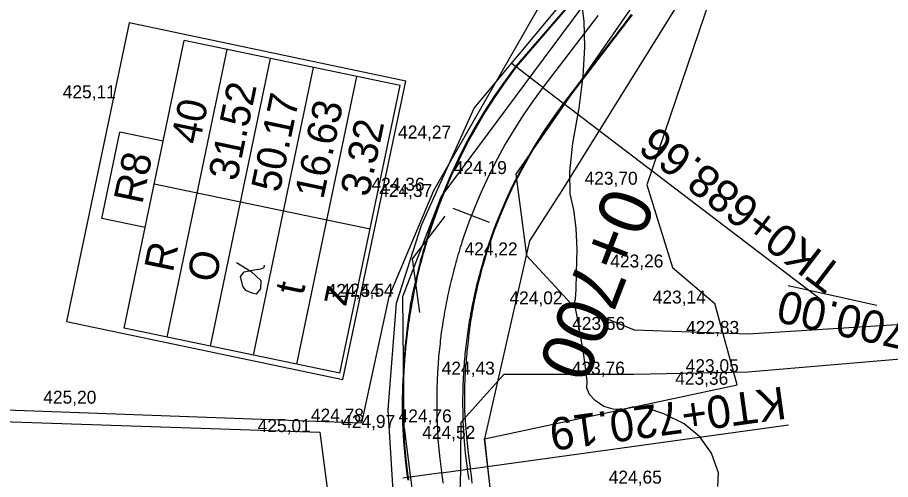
# Model space of a CAD drawing. Extents: x -574342 to -507939, y -1144044 to -1123894.
# Drawn here: x -508582.8 to -508515.5, y -1143739.5 to -1143703.9 of the extents above; entities that cross this region are included whole.
import ezdxf

# ---------------------------------------------------------------- set-up
doc = ezdxf.new("R2010")
doc.units = 0
for name, color, linetype in [('01_PARCELY_NAVRH_PC', 7, 'Continuous'), ('1000', 7, 'Continuous'), ('18', 7, 'Continuous'), ('19', 7, 'Continuous'), ('21', 7, 'Continuous'), ('23', 7, 'Continuous'), ('42', 7, 'Continuous'), ('55', 7, 'Continuous'), ('6', 7, 'Continuous'), ('Level 255', 7, 'Continuous'), ('SO 101_popis oblouku', 7, 'Continuous'), ('tab', 7, 'Continuous'), ('VRST VEDL', 7, 'Continuous')]:
    doc.layers.add(name, color=color, linetype=linetype)

msp = doc.modelspace()

# ---------------------------------------------------------------- linework, layer by layer
msp.add_lwpolyline([(-508557.691, -1143731.784), (-508552.841, -1143708.769), (-508574.145, -1143704.279), (-508578.996, -1143727.293)], close=True)
at = {"layer": '01_PARCELY_NAVRH_PC'}
for points in [[(-508550.74, -1143812.56), (-508547.51, -1143799.72), (-508547.8, -1143787.43), (-508554.08, -1143749.16), (-508553.41, -1143747.02), (-508554.21, -1143734.12), (-508553.55, -1143725.9), (-508551.64, -1143719.89), (-508547.57, -1143710.87), (-508540.84, -1143702.78), (-508531.01, -1143689.84), (-508528.88, -1143683.95), (-508518.64, -1143667.59), (-508513.88, -1143662.3), (-508507.94, -1143646.93), (-508502.84, -1143629.47), (-508500.33, -1143614.14), (-508495.09, -1143559.2), (-508493.85, -1143537.59)], [(-508550.74, -1143812.56), (-508547.51, -1143799.72), (-508547.8, -1143787.43), (-508554.08, -1143749.16), (-508553.41, -1143747.02), (-508554.21, -1143734.12), (-508553.55, -1143725.9), (-508551.64, -1143719.89), (-508547.57, -1143710.87), (-508540.84, -1143702.78), (-508531.01, -1143689.84), (-508528.88, -1143683.95), (-508518.64, -1143667.59), (-508513.88, -1143662.3), (-508507.94, -1143646.93), (-508502.84, -1143629.47), (-508500.33, -1143614.14), (-508495.09, -1143559.2), (-508493.85, -1143537.59)], [(-508488.59, -1143541.43), (-508489.82, -1143560.44), (-508491.6, -1143582.01), (-508495.73, -1143620.81), (-508499.42, -1143638.98), (-508505.75, -1143657.81), (-508517.46, -1143682.4), (-508526.71, -1143694.52), (-508540.76, -1143717.14), (-508543.32, -1143721.09), (-508546.79, -1143736.35), (-508545.73, -1143746.01), (-508540.36, -1143791.5), (-508536.1, -1143827.99)], [(-508488.59, -1143541.43), (-508489.82, -1143560.44), (-508491.6, -1143582.01), (-508495.73, -1143620.81), (-508499.42, -1143638.98), (-508505.75, -1143657.81), (-508517.46, -1143682.4), (-508526.71, -1143694.52), (-508540.76, -1143717.14), (-508543.32, -1143721.09), (-508546.79, -1143736.35), (-508545.73, -1143746.01), (-508540.36, -1143791.5), (-508536.1, -1143827.99)]]:
    msp.add_lwpolyline(points, dxfattribs=at)
at = {"layer": '1000'}
for points in [[(-508540.235, -1143702.843), (-508544.388, -1143707.644), (-508544.389, -1143707.645), (-508545.223, -1143708.771), (-508546.02, -1143709.923), (-508546.78, -1143711.1), (-508547.501, -1143712.302), (-508548.184, -1143713.526), (-508548.812, -1143714.779), (-508549.4, -1143716.051), (-508549.946, -1143717.341), (-508550.271, -1143718.166), (-508550.452, -1143718.647), (-508550.917, -1143719.969), (-508551.049, -1143720.373), (-508551.116, -1143720.581), (-508551.182, -1143720.79), (-508551.246, -1143720.999), (-508551.31, -1143721.208), (-508551.339, -1143721.304), (-508551.373, -1143721.417), (-508551.435, -1143721.627), (-508551.496, -1143721.837), (-508551.556, -1143722.047), (-508551.615, -1143722.258), (-508551.673, -1143722.469), (-508551.723, -1143722.652), (-508551.731, -1143722.68), (-508551.787, -1143722.891), (-508551.842, -1143723.102), (-508551.896, -1143723.314), (-508551.95, -1143723.526), (-508552.002, -1143723.739), (-508552.054, -1143723.951), (-508552.068, -1143724.01), (-508552.104, -1143724.164), (-508552.154, -1143724.377), (-508552.202, -1143724.59), (-508552.25, -1143724.804), (-508552.297, -1143725.018), (-508552.342, -1143725.232), (-508552.371, -1143725.378), (-508552.385, -1143725.446), (-508552.427, -1143725.661), (-508552.468, -1143725.876), (-508552.502, -1143726.092), (-508552.535, -1143726.308), (-508552.567, -1143726.525), (-508552.599, -1143726.741), (-508552.602, -1143726.761), (-508552.63, -1143726.958), (-508552.659, -1143727.175), (-508552.688, -1143727.391), (-508552.716, -1143727.608), (-508552.743, -1143727.825), (-508552.769, -1143728.042), (-508552.781, -1143728.15), (-508552.794, -1143728.26), (-508552.818, -1143728.477), (-508552.841, -1143728.694), (-508552.863, -1143728.912), (-508552.884, -1143729.129), (-508552.904, -1143729.347), (-508552.921, -1143729.544), (-508552.923, -1143729.565), (-508552.941, -1143729.783), (-508552.958, -1143730), (-508552.974, -1143730.218), (-508552.989, -1143730.436), (-508553.004, -1143730.654), (-508553.017, -1143730.873), (-508553.022, -1143730.941), (-508553.031, -1143731.091), (-508553.044, -1143731.309), (-508553.056, -1143731.527), (-508553.067, -1143731.745), (-508553.077, -1143731.964), (-508553.085, -1143732.182), (-508553.091, -1143732.339), (-508553.093, -1143732.4), (-508553.099, -1143732.619), (-508553.105, -1143732.837), (-508553.109, -1143733.056), (-508553.112, -1143733.274), (-508553.114, -1143733.493), (-508553.115, -1143733.712), (-508553.115, -1143733.739), (-508553.115, -1143733.93), (-508553.114, -1143734.149), (-508553.112, -1143734.368), (-508553.108, -1143734.586), (-508553.104, -1143734.805), (-508553.098, -1143735.023), (-508553.095, -1143735.14), (-508553.022, -1143736.539), (-508552.899, -1143737.935), (-508552.739, -1143739.24), (-508552.727, -1143739.325), (-508552.726, -1143739.33), (-508552.684, -1143739.537)], [(-508540.196, -1143702.873), (-508544.339, -1143707.682), (-508544.34, -1143707.682), (-508545.17, -1143708.809), (-508545.962, -1143709.961), (-508546.716, -1143711.14), (-508547.431, -1143712.342), (-508548.106, -1143713.567), (-508548.74, -1143714.814), (-508549.333, -1143716.081), (-508549.885, -1143717.366), (-508550.212, -1143718.189), (-508550.393, -1143718.669), (-508550.859, -1143719.988), (-508550.992, -1143720.392), (-508551.059, -1143720.6), (-508551.124, -1143720.808), (-508551.189, -1143721.016), (-508551.252, -1143721.225), (-508551.281, -1143721.322), (-508551.315, -1143721.435), (-508551.376, -1143721.644), (-508551.436, -1143721.854), (-508551.496, -1143722.064), (-508551.554, -1143722.275), (-508551.611, -1143722.485), (-508551.659, -1143722.669), (-508551.667, -1143722.696), (-508551.722, -1143722.908), (-508551.775, -1143723.119), (-508551.828, -1143723.331), (-508551.88, -1143723.543), (-508551.93, -1143723.756), (-508551.98, -1143723.968), (-508551.993, -1143724.027), (-508552.028, -1143724.181), (-508552.075, -1143724.394), (-508552.122, -1143724.608), (-508552.167, -1143724.821), (-508552.211, -1143725.035), (-508552.253, -1143725.249), (-508552.282, -1143725.396), (-508552.295, -1143725.464), (-508552.336, -1143725.678), (-508552.376, -1143725.893), (-508552.414, -1143726.108), (-508552.451, -1143726.323), (-508552.488, -1143726.538), (-508552.523, -1143726.754), (-508552.526, -1143726.773), (-508552.557, -1143726.969), (-508552.59, -1143727.185), (-508552.622, -1143727.401), (-508552.653, -1143727.617), (-508552.682, -1143727.833), (-508552.711, -1143728.05), (-508552.724, -1143728.158), (-508552.738, -1143728.267), (-508552.764, -1143728.483), (-508552.79, -1143728.7), (-508552.814, -1143728.917), (-508552.837, -1143729.134), (-508552.859, -1143729.351), (-508552.877, -1143729.548), (-508552.879, -1143729.569), (-508552.899, -1143729.786), (-508552.917, -1143730.004), (-508552.935, -1143730.221), (-508552.951, -1143730.439), (-508552.966, -1143730.657), (-508552.98, -1143730.875), (-508552.985, -1143730.943), (-508552.993, -1143731.093), (-508553.005, -1143731.311), (-508553.016, -1143731.529), (-508553.026, -1143731.747), (-508553.034, -1143731.965), (-508553.041, -1143732.183), (-508553.046, -1143732.34), (-508553.048, -1143732.402), (-508553.053, -1143732.62), (-508553.057, -1143732.838), (-508553.06, -1143733.056), (-508553.061, -1143733.275), (-508553.062, -1143733.493), (-508553.062, -1143733.711), (-508553.061, -1143733.739), (-508553.06, -1143733.93), (-508553.057, -1143734.148), (-508553.053, -1143734.366), (-508553.048, -1143734.585), (-508553.042, -1143734.803), (-508553.035, -1143735.021), (-508553.031, -1143735.137), (-508552.955, -1143736.534), (-508552.832, -1143737.928), (-508552.676, -1143739.231), (-508552.664, -1143739.316), (-508552.664, -1143739.321), (-508552.622, -1143739.528)], [(-508535.464, -1143703.627), (-508535.66, -1143703.885), (-508535.857, -1143704.142), (-508536.053, -1143704.4), (-508536.25, -1143704.658), (-508536.447, -1143704.916), (-508536.643, -1143705.174), (-508536.84, -1143705.432), (-508540.681, -1143710.47), (-508540.682, -1143710.471), (-508541.422, -1143711.476), (-508542.129, -1143712.504), (-508542.801, -1143713.555), (-508543.439, -1143714.628), (-508544.041, -1143715.721), (-508544.607, -1143716.833), (-508545.136, -1143717.963), (-508545.628, -1143719.109), (-508545.919, -1143719.843), (-508546.082, -1143720.272), (-508546.497, -1143721.448), (-508546.616, -1143721.808), (-508546.675, -1143721.994), (-508546.734, -1143722.179), (-508546.791, -1143722.365), (-508546.848, -1143722.552), (-508546.874, -1143722.638), (-508546.903, -1143722.738), (-508546.958, -1143722.925), (-508547.012, -1143723.113), (-508547.065, -1143723.3), (-508547.117, -1143723.488), (-508547.167, -1143723.676), (-508547.211, -1143723.839), (-508547.217, -1143723.864), (-508547.266, -1143724.052), (-508547.314, -1143724.241), (-508547.361, -1143724.43), (-508547.407, -1143724.619), (-508547.452, -1143724.809), (-508547.497, -1143724.999), (-508547.509, -1143725.051), (-508547.54, -1143725.188), (-508547.582, -1143725.379), (-508547.623, -1143725.569), (-508547.663, -1143725.76), (-508547.703, -1143725.95), (-508547.741, -1143726.141), (-508547.766, -1143726.272), (-508547.778, -1143726.332), (-508547.814, -1143726.524), (-508547.85, -1143726.715), (-508547.884, -1143726.907), (-508547.917, -1143727.099), (-508547.95, -1143727.291), (-508547.981, -1143727.483), (-508547.984, -1143727.5), (-508548.011, -1143727.675), (-508548.041, -1143727.868), (-508548.069, -1143728.061), (-508548.097, -1143728.253), (-508548.123, -1143728.446), (-508548.149, -1143728.639), (-508548.161, -1143728.736), (-508548.173, -1143728.833), (-508548.197, -1143729.026), (-508548.219, -1143729.219), (-508548.241, -1143729.413), (-508548.261, -1143729.607), (-508548.281, -1143729.8), (-508548.297, -1143729.976), (-508548.299, -1143729.994), (-508548.317, -1143730.188), (-508548.333, -1143730.382), (-508548.349, -1143730.577), (-508548.363, -1143730.771), (-508548.377, -1143730.965), (-508548.389, -1143731.159), (-508548.393, -1143731.22), (-508548.401, -1143731.354), (-508548.411, -1143731.548), (-508548.421, -1143731.743), (-508548.429, -1143731.937), (-508548.437, -1143732.132), (-508548.444, -1143732.327), (-508548.448, -1143732.467), (-508548.449, -1143732.521), (-508548.454, -1143732.716), (-508548.457, -1143732.911), (-508548.46, -1143733.105), (-508548.461, -1143733.3), (-508548.462, -1143733.495), (-508548.462, -1143733.69), (-508548.461, -1143733.714), (-508548.46, -1143733.884), (-508548.458, -1143734.079), (-508548.454, -1143734.274), (-508548.45, -1143734.469), (-508548.444, -1143734.663), (-508548.438, -1143734.858), (-508548.434, -1143734.962), (-508548.366, -1143736.208), (-508548.257, -1143737.451), (-508548.118, -1143738.613), (-508548.107, -1143738.689), (-508548.107, -1143738.694), (-508548.078, -1143738.903), (-508548.038, -1143739.197), (-508547.997, -1143739.49)], [(-508535.409, -1143703.668), (-508535.608, -1143703.925), (-508535.805, -1143704.182), (-508536.001, -1143704.44), (-508536.198, -1143704.698), (-508536.395, -1143704.955), (-508536.593, -1143705.213), (-508536.79, -1143705.47), (-508540.644, -1143710.499), (-508540.644, -1143710.5), (-508541.384, -1143711.503), (-508542.089, -1143712.531), (-508542.759, -1143713.581), (-508543.392, -1143714.655), (-508543.987, -1143715.749), (-508544.556, -1143716.858), (-508545.083, -1143717.986), (-508545.572, -1143719.132), (-508545.862, -1143719.865), (-508546.023, -1143720.294), (-508546.436, -1143721.469), (-508546.554, -1143721.828), (-508546.613, -1143722.013), (-508546.671, -1143722.199), (-508546.728, -1143722.385), (-508546.784, -1143722.571), (-508546.809, -1143722.657), (-508546.838, -1143722.758), (-508546.892, -1143722.944), (-508546.945, -1143723.132), (-508546.996, -1143723.319), (-508547.047, -1143723.507), (-508547.098, -1143723.694), (-508547.141, -1143723.858), (-508547.147, -1143723.882), (-508547.196, -1143724.071), (-508547.243, -1143724.259), (-508547.289, -1143724.448), (-508547.334, -1143724.637), (-508547.378, -1143724.826), (-508547.421, -1143725.016), (-508547.432, -1143725.068), (-508547.462, -1143725.206), (-508547.503, -1143725.396), (-508547.542, -1143725.586), (-508547.581, -1143725.777), (-508547.618, -1143725.967), (-508547.654, -1143726.158), (-508547.678, -1143726.289), (-508547.689, -1143726.349), (-508547.723, -1143726.541), (-508547.756, -1143726.732), (-508547.788, -1143726.924), (-508547.818, -1143727.116), (-508547.848, -1143727.308), (-508547.876, -1143727.5), (-508547.879, -1143727.517), (-508547.903, -1143727.692), (-508547.93, -1143727.885), (-508547.955, -1143728.077), (-508547.978, -1143728.27), (-508548.001, -1143728.463), (-508548.023, -1143728.656), (-508548.033, -1143728.752), (-508548.043, -1143728.849), (-508548.063, -1143729.042), (-508548.081, -1143729.235), (-508548.104, -1143729.428), (-508548.126, -1143729.621), (-508548.147, -1143729.814), (-508548.164, -1143729.988), (-508548.166, -1143730.007), (-508548.185, -1143730.2), (-508548.202, -1143730.393), (-508548.218, -1143730.587), (-508548.234, -1143730.78), (-508548.247, -1143730.974), (-508548.26, -1143731.167), (-508548.264, -1143731.228), (-508548.272, -1143731.361), (-508548.282, -1143731.555), (-508548.292, -1143731.749), (-508548.3, -1143731.943), (-508548.307, -1143732.137), (-508548.313, -1143732.331), (-508548.316, -1143732.47), (-508548.317, -1143732.525), (-508548.321, -1143732.719), (-508548.323, -1143732.913), (-508548.325, -1143733.107), (-508548.325, -1143733.301), (-508548.324, -1143733.495), (-508548.322, -1143733.689), (-508548.321, -1143733.713), (-508548.318, -1143733.883), (-508548.314, -1143734.077), (-508548.308, -1143734.271), (-508548.301, -1143734.465), (-508548.293, -1143734.659), (-508548.274, -1143734.852), (-508548.261, -1143734.955), (-508548.155, -1143736.193), (-508548.038, -1143737.428), (-508547.884, -1143738.582), (-508547.872, -1143738.657), (-508547.871, -1143738.662), (-508547.845, -1143738.871), (-508547.817, -1143739.166), (-508547.789, -1143739.462), (-508547.76, -1143739.757)]]:
    msp.add_lwpolyline(points, dxfattribs=at)
at = {"layer": '21'}
msp.add_lwpolyline([(-508538.037, -1143703.704), (-508538.234, -1143703.961), (-508538.43, -1143704.219), (-508542.272, -1143709.258), (-508542.272, -1143709.259), (-508543.051, -1143710.316), (-508543.795, -1143711.399), (-508544.503, -1143712.505), (-508545.174, -1143713.634), (-508545.808, -1143714.784), (-508546.404, -1143715.955), (-508546.961, -1143717.144), (-508547.479, -1143718.351), (-508547.785, -1143719.124), (-508547.956, -1143719.575), (-508548.394, -1143720.813), (-508548.518, -1143721.192), (-508548.581, -1143721.388), (-508548.643, -1143721.583), (-508548.703, -1143721.779), (-508548.763, -1143721.975), (-508548.79, -1143722.066), (-508548.821, -1143722.172), (-508548.879, -1143722.368), (-508548.936, -1143722.565), (-508548.991, -1143722.763), (-508549.046, -1143722.96), (-508549.099, -1143723.158), (-508549.145, -1143723.33), (-508549.152, -1143723.356), (-508549.203, -1143723.555), (-508549.254, -1143723.753), (-508549.303, -1143723.952), (-508549.352, -1143724.152), (-508549.399, -1143724.351), (-508549.446, -1143724.551), (-508549.458, -1143724.606), (-508549.491, -1143724.751), (-508549.536, -1143724.951), (-508549.579, -1143725.151), (-508549.621, -1143725.352), (-508549.663, -1143725.552), (-508549.703, -1143725.753), (-508549.73, -1143725.891), (-508549.742, -1143725.955), (-508549.78, -1143726.156), (-508549.817, -1143726.358), (-508549.854, -1143726.559), (-508549.889, -1143726.761), (-508549.923, -1143726.964), (-508549.956, -1143727.166), (-508549.959, -1143727.184), (-508549.988, -1143727.368), (-508550.019, -1143727.571), (-508550.049, -1143727.774), (-508550.078, -1143727.977), (-508550.105, -1143728.18), (-508550.132, -1143728.383), (-508550.145, -1143728.484), (-508550.158, -1143728.587), (-508550.183, -1143728.79), (-508550.206, -1143728.994), (-508550.229, -1143729.197), (-508550.25, -1143729.401), (-508550.271, -1143729.605), (-508550.289, -1143729.79), (-508550.29, -1143729.809), (-508550.309, -1143730.014), (-508550.326, -1143730.218), (-508550.343, -1143730.422), (-508550.358, -1143730.627), (-508550.372, -1143730.831), (-508550.385, -1143731.036), (-508550.389, -1143731.099), (-508550.398, -1143731.24), (-508550.409, -1143731.445), (-508550.419, -1143731.65), (-508550.428, -1143731.855), (-508550.436, -1143732.059), (-508550.443, -1143732.264), (-508550.447, -1143732.412), (-508550.448, -1143732.469), (-508550.453, -1143732.674), (-508550.457, -1143732.879), (-508550.46, -1143733.084), (-508550.461, -1143733.289), (-508550.462, -1143733.494), (-508550.462, -1143733.699), (-508550.461, -1143733.725), (-508550.46, -1143733.904), (-508550.458, -1143734.109), (-508550.454, -1143734.314), (-508550.449, -1143734.519), (-508550.444, -1143734.724), (-508550.437, -1143734.929), (-508550.433, -1143735.038), (-508550.361, -1143736.35), (-508550.246, -1143737.658), (-508550.1, -1143738.882), (-508550.089, -1143738.962), (-508550.088, -1143738.967), (-508550.059, -1143739.176), (-508550.019, -1143739.469), (-508549.978, -1143739.763)], dxfattribs=at)
at = {"layer": '23'}
for points in [[(-508542.272, -1143709.259), (-508544.658, -1143707.44)], [(-508542.272, -1143709.259), (-508520.8, -1143725.628)], [(-508550.089, -1143738.962), (-508523.341, -1143735.282)], [(-508550.089, -1143738.962), (-508553.061, -1143739.371)]]:
    msp.add_lwpolyline(points, dxfattribs=at)
msp.add_lwpolyline([(-508648.99, -1143732.84), (-508559.47, -1143735.83), (-508555.12, -1143769), (-508649.91, -1143765.94)], close=True, dxfattribs=at)
msp.add_lwpolyline([(-508648.99, -1143732.84), (-508559.47, -1143735.83), (-508555.12, -1143769), (-508649.91, -1143765.94)], close=True, dxfattribs=at)
at = {"layer": '42'}
for points in [[(-508504.21, -1143312.1), (-508501.69, -1143337.29), (-508498.26, -1143372.94), (-508494.88, -1143409.3), (-508491.01, -1143461.13), (-508489.31, -1143484.85), (-508488.03, -1143504.43), (-508488.95, -1143532.56), (-508489.82, -1143560.44), (-508491.6, -1143582.01), (-508495.73, -1143620.81), (-508499.42, -1143638.98), (-508505.75, -1143657.81), (-508512.68, -1143673.17), (-508526.71, -1143694.52), (-508534.28, -1143716.76), (-508532.3, -1143723.14), (-508529.03, -1143725.92)], [(-508504.21, -1143312.1), (-508501.69, -1143337.29), (-508498.26, -1143372.94), (-508494.88, -1143409.3), (-508491.01, -1143461.13), (-508489.31, -1143484.85), (-508488.03, -1143504.43), (-508488.95, -1143532.56), (-508489.82, -1143560.44), (-508491.6, -1143582.01), (-508495.73, -1143620.81), (-508499.42, -1143638.98), (-508505.75, -1143657.81), (-508512.68, -1143673.17), (-508526.71, -1143694.52), (-508534.28, -1143716.76), (-508532.3, -1143723.14), (-508529.03, -1143725.92)], [(-508538.41, -1143695.73), (-508550.7, -1143717.22), (-508554.15, -1143725.41), (-508556.26, -1143735.12)], [(-508538.41, -1143695.73), (-508550.7, -1143717.22), (-508554.15, -1143725.41), (-508556.26, -1143735.12)], [(-508705.85, -1143964.71), (-508677.04, -1143948.2), (-508689.78, -1143863.38), (-508555.59, -1143821.12), (-508536.1, -1143827.99), (-508546.79, -1143736.35), (-508527.3, -1143732.18), (-508529.03, -1143725.92)], [(-508705.85, -1143964.71), (-508677.04, -1143948.2), (-508689.78, -1143863.38), (-508555.59, -1143821.12), (-508536.1, -1143827.99), (-508546.79, -1143736.35), (-508527.3, -1143732.18), (-508529.03, -1143725.92)], [(-508783.56, -1143737.45), (-508767.97, -1143732.44), (-508753.43, -1143729.51), (-508742.89, -1143728.11), (-508614.52, -1143732.98), (-508556.26, -1143735.12)], [(-508783.56, -1143737.45), (-508767.97, -1143732.44), (-508753.43, -1143729.51), (-508742.89, -1143728.11), (-508614.52, -1143732.98), (-508556.26, -1143735.12)]]:
    msp.add_lwpolyline(points, dxfattribs=at)
at = {"layer": '55'}
for points in [[(-508552.96, -1143735.51), (-508553.08, -1143725.38), (-508550.11, -1143717.7), (-508537.92, -1143701.24), (-508527.34, -1143687.8)], [(-508552.96, -1143735.51), (-508553.08, -1143725.38), (-508550.11, -1143717.7), (-508537.92, -1143701.24), (-508527.34, -1143687.8)], [(-508525.32, -1143690.09), (-508535.59, -1143703.27), (-508544.36, -1143715.94), (-508543.53, -1143722.21), (-508540.07, -1143725.98), (-508535.24, -1143727.95)], [(-508525.32, -1143690.09), (-508535.59, -1143703.27), (-508544.36, -1143715.94), (-508543.53, -1143722.21), (-508540.07, -1143725.98), (-508535.24, -1143727.95)], [(-508535.24, -1143727.95), (-508526.46, -1143728.26), (-508501.11, -1143726.66), (-508465.73, -1143720.83), (-508436.38, -1143717.34), (-508404.62, -1143713), (-508392.89, -1143708.57)], [(-508535.24, -1143727.95), (-508526.46, -1143728.26), (-508501.11, -1143726.66), (-508465.73, -1143720.83), (-508436.38, -1143717.34), (-508404.62, -1143713), (-508392.89, -1143708.57)], [(-508392.18, -1143711.54), (-508404.03, -1143715.66), (-508436.06, -1143720.68), (-508465.22, -1143724.02), (-508500.81, -1143729.03), (-508526.49, -1143731.21), (-508535.27, -1143731.4)], [(-508392.18, -1143711.54), (-508404.03, -1143715.66), (-508436.06, -1143720.68), (-508465.22, -1143724.02), (-508500.81, -1143729.03), (-508526.49, -1143731.21), (-508535.27, -1143731.4)], [(-508535.27, -1143731.4), (-508545.29, -1143731.4), (-508548.61, -1143735.08)], [(-508535.27, -1143731.4), (-508545.29, -1143731.4), (-508548.61, -1143735.08)], [(-508548.61, -1143735.08), (-508548.65, -1143740.56), (-508547.87, -1143747.22), (-508545.1, -1143768.03), (-508541.4, -1143799.09), (-508540.43, -1143820.16), (-508537.93, -1143851.28), (-508535.31, -1143876.1), (-508531.43, -1143907.19), (-508528.41, -1143930.89), (-508527.67, -1143936.89)], [(-508548.61, -1143735.08), (-508548.65, -1143740.56), (-508547.87, -1143747.22), (-508545.1, -1143768.03), (-508541.4, -1143799.09), (-508540.43, -1143820.16), (-508537.93, -1143851.28), (-508535.31, -1143876.1), (-508531.43, -1143907.19), (-508528.41, -1143930.89), (-508527.67, -1143936.89)], [(-508552.96, -1143735.51), (-508552.22, -1143741.39), (-508550.83, -1143747.83), (-508547.65, -1143771.75), (-508544.7, -1143799.69), (-508543.59, -1143814.54)], [(-508552.96, -1143735.51), (-508552.22, -1143741.39), (-508550.83, -1143747.83), (-508547.65, -1143771.75), (-508544.7, -1143799.69), (-508543.59, -1143814.54)]]:
    msp.add_lwpolyline(points, dxfattribs=at)
at = {"layer": '6'}
for points in [[(-508546.386, -1143719.663), (-508549.185, -1143718.584)], [(-508547.785, -1143719.124), (-508547.785, -1143719.124)], [(-508516.546, -1143726.077), (-508523.379, -1143724.556)]]:
    msp.add_lwpolyline(points, dxfattribs=at)
at = {"layer": 'SO 101_popis oblouku'}
for p, q in [((-508574.555, -1143727.821), (-508569.927, -1143705.632)), ((-508553.285, -1143709.103), (-508569.927, -1143705.632)), ((-508571.227, -1143728.515), (-508566.599, -1143706.326)), ((-508567.899, -1143729.21), (-508563.27, -1143707.021)), ((-508564.57, -1143729.904), (-508559.942, -1143707.715)), ((-508561.242, -1143730.598), (-508556.614, -1143708.409)), ((-508557.914, -1143731.292), (-508553.285, -1143709.103)), ((-508576.264, -1143719.361), (-508574.875, -1143712.704)), ((-508571.547, -1143713.398), (-508574.875, -1143712.704)), ((-508555.599, -1143720.198), (-508572.241, -1143716.727)), ((-508572.935, -1143720.055), (-508576.264, -1143719.361)), ((-508557.914, -1143731.292), (-508574.555, -1143727.821))]:
    msp.add_line(p, q, dxfattribs=at)
msp.add_lwpolyline([(-508565.882, -1143722.758), (-508564.753, -1143723.439), (-508564.005, -1143724.156), (-508564.038, -1143724.788), (-508564.362, -1143725.186), (-508564.69, -1143725.124), (-508565.165, -1143724.924), (-508565.406, -1143724.571), (-508565.571, -1143723.831), (-508565.3, -1143723.468), (-508564.531, -1143723.329), (-508564.017, -1143723.247), (-508563.766, -1143723.147), (-508563.729, -1143722.968)], dxfattribs=at)
at = {"layer": 'tab'}
msp.add_lwpolyline([(-508549.835, -1143719.179), (-508552.356, -1143722.485), (-508551.789, -1143726.604)], dxfattribs=at)
at = {"layer": 'VRST VEDL'}
msp.add_lwpolyline([(-508528.802, -1143740.034), (-508528.749, -1143738.968), (-508529.295, -1143737.464), (-508530.176, -1143736.207), (-508531.394, -1143735.195), (-508532.948, -1143734.43), (-508534.252, -1143733.99), (-508535.306, -1143733.874), (-508536.11, -1143734.083), (-508536.868, -1143734.075), (-508537.579, -1143733.849), (-508538.243, -1143733.406), (-508538.681, -1143732.937), (-508538.892, -1143732.442), (-508538.875, -1143731.921), (-508538.958, -1143731.018), (-508539.14, -1143729.732), (-508539.42, -1143728.065), (-508539.625, -1143726.916), (-508539.754, -1143726.286), (-508539.807, -1143726.176), (-508539.843, -1143726.085), (-508539.862, -1143726.012), (-508539.864, -1143725.959), (-508539.847, -1143725.867), (-508539.813, -1143725.738), (-508539.761, -1143725.571), (-508539.715, -1143724.848), (-508539.678, -1143723.571), (-508539.647, -1143721.737), (-508539.719, -1143720.11), (-508539.895, -1143718.689), (-508540.173, -1143717.473), (-508540.196, -1143715.765), (-508539.963, -1143713.563), (-508539.474, -1143710.869), (-508539.166, -1143708.403), (-508539.041, -1143706.165), (-508539.096, -1143704.155), (-508539.265, -1143702.735)], dxfattribs=at)

# ---------------------------------------------------------------- texts
at = {"layer": '18'}
for s, height, rotation, p in [('TK0+688.66', 2.5, 142.67945, (-508518.982, -1143723.242)), ('0+700', 4, 248.9213, (-508537.283, -1143716.715)), ('KT0+720.19', 2.5, 187.83426, (-508523.75, -1143732.31))]:
    msp.add_text(s, height=height, rotation=rotation, dxfattribs=at).set_placement(p)
at = {"layer": '19'}
msp.add_text('P14   700.00', height=2.5, rotation=167.45219, dxfattribs=at).set_placement((-508505.348, -1143728.979))
at = {"layer": 'Level 255'}
for s, p in [('425,11', (-508579.275, -1143710.1)), ('424,27', (-508553.435, -1143713.2)), ('424,19', (-508549.145, -1143715.94)), ('423,70', (-508539.065, -1143716.76)), ('424,36', (-508555.485, -1143717.22)), ('424,37', (-508554.895, -1143717.7)), ('424,22', (-508548.315, -1143722.21)), ('423,26', (-508537.085, -1143723.14)), ('424,54', (-508558.935, -1143725.41)), ('424,54', (-508557.865, -1143725.38)), ('424,02', (-508544.855, -1143725.98)), ('423,14', (-508533.815, -1143725.92)), ('423,56', (-508540.025, -1143727.95)), ('422,83', (-508531.245, -1143728.26)), ('424,43', (-508550.075, -1143731.4)), ('423,76', (-508540.055, -1143731.4)), ('423,05', (-508531.275, -1143731.21)), ('423,36', (-508532.085, -1143732.18)), ('425,20', (-508580.775, -1143733.64)), ('424,78', (-508560.155, -1143735.02)), ('424,97', (-508557.745, -1143735.51)), ('424,76', (-508553.395, -1143735.08)), ('425,01', (-508564.255, -1143735.83)), ('424,52', (-508551.575, -1143736.35)), ('424,65', (-508537.205, -1143739.8))]:
    msp.add_text(s, height=1, dxfattribs=at).set_placement(p)
at = {"layer": 'SO 101_popis oblouku'}
for s, height, p in [('31.52', 2.2667, (-508565.861, -1143716.556)), ('50.17', 2.2667, (-508562.569, -1143717.428)), ('40', 2.2667, (-508568.745, -1143713.735)), ('16.63', 2.2667, (-508559.204, -1143717.945)), ('3.32', 2.2667, (-508555.694, -1143717.767)), ('R8', 2.2667, (-508573.153, -1143718.323)), ('R', 2.267, (-508570.8, -1143723.588)), ('O', 2.267, (-508567.494, -1143724.388)), ('t', 2.267, (-508560.749, -1143725.353)), ('z', 2.267, (-508557.454, -1143726.206))]:
    msp.add_text(s, height=height, rotation=78.21271, dxfattribs=at).set_placement(p)

doc.saveas('drawing.dxf')
